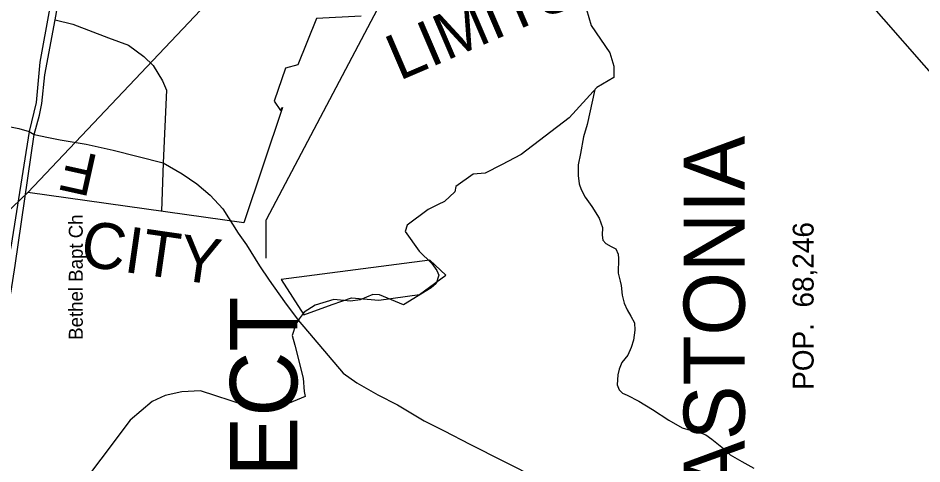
# Model space of a CAD drawing. Extents: x 1372027 to 1374286, y 553832 to 556743.
# Drawn here: x 1373235 to 1373346.9, y 554120.7 to 554175.8 of the extents above; entities that cross this region are included whole.
import ezdxf

# ---------------------------------------------------------------- set-up
doc = ezdxf.new("R2010")
doc.units = 0
for name, color, linetype in [('Default', 7, 'Continuous'), ('Prop DGN Element Guardrail', 7, 'Continuous'), ('Prop Dimension', 7, 'Continuous'), ('Prop Dimension Text', 7, 'Continuous'), ('Prop Paved Shoulder', 7, 'Continuous'), ('Sheet Clip Boundary CELL', 7, 'Continuous'), ('Sheet North Arrow Point CELL', 7, 'Continuous'), ('Sheet Plot Border Outside CELL', 7, 'Continuous'), ('Sheet Sticker Preliminary CELL', 7, 'Continuous')]:
    doc.layers.add(name, color=color, linetype=linetype)

msp = doc.modelspace()

# ---------------------------------------------------------------- linework, layer by layer
at = {"layer": 'Prop DGN Element Guardrail'}
for points in [[(1373243.39, 554203.71), (1373243.11, 554201.73), (1373241.82, 554193.42), (1373241.04, 554188.77), (1373239.73, 554181.91), (1373238.91, 554176.94), (1373237.72, 554170.38), (1373237.26, 554165.39), (1373236.4, 554161.79)], [(1373239.62, 554175.59), (1373244.38, 554201.97), (1373244.68, 554203.58)], [(1373237.01, 554161.45), (1373237.68, 554163.82), (1373237.97, 554165.25), (1373238.34, 554168.81), (1373239.62, 554175.59)], [(1373236.4, 554161.79), (1373234.18, 554147.73), (1373232.59, 554139.9), (1373231.98, 554135.75), (1373229.87, 554122.96)], [(1373230.77, 554122.61), (1373233.13, 554136.43), (1373234.2, 554142.04), (1373234.7, 554145.22), (1373237.01, 554161.45)]]:
    msp.add_lwpolyline(points, dxfattribs=at)
at = {"layer": 'Prop Dimension'}
for p, q in [((1373297.7, 554211.34), (1373265.72, 554150.9)), ((1373310.79, 554211.65), (1373352.15, 554164.19)), ((1373265.73, 554146.14), (1373265.72, 554150.9))]:
    msp.add_line(p, q, dxfattribs=at)
for points in [[(1373305.38, 554176.88), (1373305.92, 554174.9), (1373308.25, 554171.54), (1373308.73, 554169.89), (1373308.73, 554168.49), (1373306.64, 554167.26), (1373303.23, 554163.49), (1373297.29, 554158.94), (1373294.84, 554157.68), (1373292.83, 554156.66), (1373292.35, 554156.6), (1373291.33, 554156.54), (1373289.18, 554154.99), (1373289.06, 554154.33), (1373287.8, 554153.13), (1373287.02, 554152.77), (1373285.76, 554152.17), (1373283.18, 554150.2), (1373282.94, 554149.42), (1373284.68, 554147.02), (1373286.24, 554145.47), (1373286.84, 554144.63), (1373287.08, 554144.03)], [(1373287.08, 554144.03), (1373286.78, 554143.01), (1373286.16, 554142.48), (1373282.73, 554140.35), (1373279.75, 554141.6), (1373278.91, 554141.65), (1373277.38, 554141), (1373276.17, 554140.83), (1373274.09, 554141.01), (1373271.79, 554140.32), (1373270.44, 554139.45), (1373269.82, 554138.65), (1373269.4, 554138), (1373268.95, 554136.57), (1373269.27, 554135.37), (1373270.29, 554131.3), (1373270.44, 554129.64), (1373270.54, 554129.04), (1373268.07, 554127.99), (1373264.24, 554127.53), (1373263.16, 554127.94), (1373257.61, 554129.72), (1373255.28, 554129.63), (1373253.24, 554129.15), (1373251.62, 554128.43), (1373248.91, 554126.1), (1373241.66, 554116.47)]]:
    msp.add_lwpolyline(points, dxfattribs=at)
at = {"layer": 'Prop Dimension Text'}
for p, q in [((1373236.26, 554154.25), (1373273.51, 554193.6)), ((1373271.95, 554175.77), (1373269.67, 554170.04)), ((1373277.47, 554176.07), (1373271.95, 554175.77)), ((1373268.13, 554169.65), (1373266.72, 554165.54)), ((1373269.67, 554170.04), (1373268.13, 554169.65)), ((1373266.72, 554165.54), (1373267.49, 554164.39)), ((1373267.75, 554164.77), (1373262.99, 554150.52)), ((1373267.49, 554164.39), (1373267.75, 554164.77)), ((1373223.54, 554142.18), (1373236.26, 554154.25)), ((1373262.99, 554150.52), (1373236.26, 554154.25)), ((1373267.57, 554143.49), (1373270.38, 554139.13))]:
    msp.add_line(p, q, dxfattribs=at)
msp.add_lwpolyline([(1373270.38, 554139.13), (1373273.9, 554140.4), (1373276.29, 554141.24), (1373279.66, 554140.96), (1373284.72, 554141.66), (1373287.96, 554144.05), (1373285.99, 554145.88), (1373267.57, 554143.49)], dxfattribs=at)
at = {"layer": 'Prop Paved Shoulder'}
for p, q in [((1373236.4, 554161.79), (1373237.01, 554161.45)), ((1373252.97, 554157.94), (1373252.78, 554151.95))]:
    msp.add_line(p, q, dxfattribs=at)
for points in [[(1373239.62, 554175.59), (1373241.81, 554175.08), (1373246.24, 554173.38), (1373248.69, 554172.49), (1373250.6, 554171.06), (1373251.76, 554169.97), (1373252.92, 554168.06), (1373253.41, 554166.92), (1373252.97, 554157.94)], [(1373209.07, 554168.11), (1373210.79, 554167.73), (1373218.72, 554165.99), (1373233.06, 554162.6), (1373235.14, 554162.18), (1373236.4, 554161.79)], [(1373237.01, 554161.45), (1373238.79, 554161.04), (1373240.23, 554160.77), (1373243.47, 554160.24), (1373246.82, 554159.5), (1373252.97, 554157.94)], [(1373252.97, 554157.94), (1373255.35, 554156.57), (1373257.16, 554155.34), (1373258.8, 554153.94), (1373260.37, 554152.22), (1373262.25, 554149.22), (1373263.31, 554147.78), (1373264.91, 554145.21), (1373266.1, 554143.42), (1373268, 554140.74), (1373269.7, 554138.49)], [(1373269.7, 554138.49), (1373275.27, 554131.93), (1373276.94, 554130.72), (1373279.56, 554129.25), (1373281.97, 554127.99), (1373285.29, 554126.04), (1373287.76, 554124.81), (1373290.92, 554123.16), (1373299.35, 554118.91)]]:
    msp.add_lwpolyline(points, dxfattribs=at)
at = {"layer": 'Sheet Plot Border Outside CELL'}
msp.add_line((1373269.72, 554138.52), (1373269.72, 554138.52), dxfattribs=at)
at = {"layer": 'Sheet Sticker Preliminary CELL'}
msp.add_lwpolyline([(1373306.41, 554167), (1373305.45, 554162.66), (1373305.01, 554161.15), (1373304.62, 554159.1), (1373304.35, 554157.68), (1373304.33, 554156.38), (1373304.46, 554155.32), (1373304.7, 554154.61), (1373305.18, 554153.67), (1373306.04, 554152.52), (1373306.94, 554151.07), (1373307.33, 554149.93), (1373307.31, 554149), (1373307.39, 554148.37), (1373307.76, 554147.94), (1373308.42, 554147.59), (1373309, 554147.29), (1373309.28, 554146.65), (1373309.32, 554146.1), (1373309.27, 554144.3), (1373309.54, 554143.29), (1373309.67, 554142.78), (1373309.77, 554141.56), (1373310.01, 554140.59), (1373310.4, 554139.74), (1373310.85, 554138.97), (1373311.3, 554138.16), (1373311.35, 554137.24), (1373311.17, 554136.02), (1373310.89, 554135.1), (1373310.46, 554134.15), (1373309.72, 554133.24), (1373309.41, 554132.41), (1373309.22, 554131.73), (1373309.21, 554131.11), (1373309.16, 554130.48), (1373309.39, 554129.88), (1373309.81, 554129.45), (1373310.4, 554129.19), (1373311.85, 554128.45), (1373313.51, 554127.44), (1373315.54, 554126.1), (1373317.21, 554125.18), (1373317.91, 554124.96), (1373319.04, 554124.72), (1373320.12, 554124.28), (1373320.87, 554123.76), (1373322.31, 554122.6), (1373323.14, 554121.82), (1373324.59, 554120.99), (1373326.05, 554120.17)], dxfattribs=at)

# ---------------------------------------------------------------- texts
at = {"layer": 'Default'}
msp.add_text('END PROJECT', height=8.3303, rotation=90.0509, dxfattribs=at).set_placement((1373269.65, 554062.79))
at = {"layer": 'Sheet Clip Boundary CELL'}
for s, height, rotation, p in [('LIMITS', 5.67, 23.2658, (1373282.21, 554168.04)), ('GASTONIA', 7.56, 90, (1373324.94, 554109.04)), ('CITY', 5.67, 351.8276, (1373242.57, 554145.24)), ('POP.  68,246', 2.5837, 90, (1373333.46, 554129.86))]:
    msp.add_text(s, height=height, rotation=rotation, dxfattribs=at).set_placement(p)
at = {"layer": 'Sheet North Arrow Point CELL'}
for s, height, rotation, p in [('F', 5.17, 167.4811, (1373245.17, 554158.8)), ('Bethel Bapt Ch', 1.7224, 90, (1373243.04, 554136.05))]:
    msp.add_text(s, height=height, rotation=rotation, dxfattribs=at).set_placement(p)

doc.saveas('drawing.dxf')
